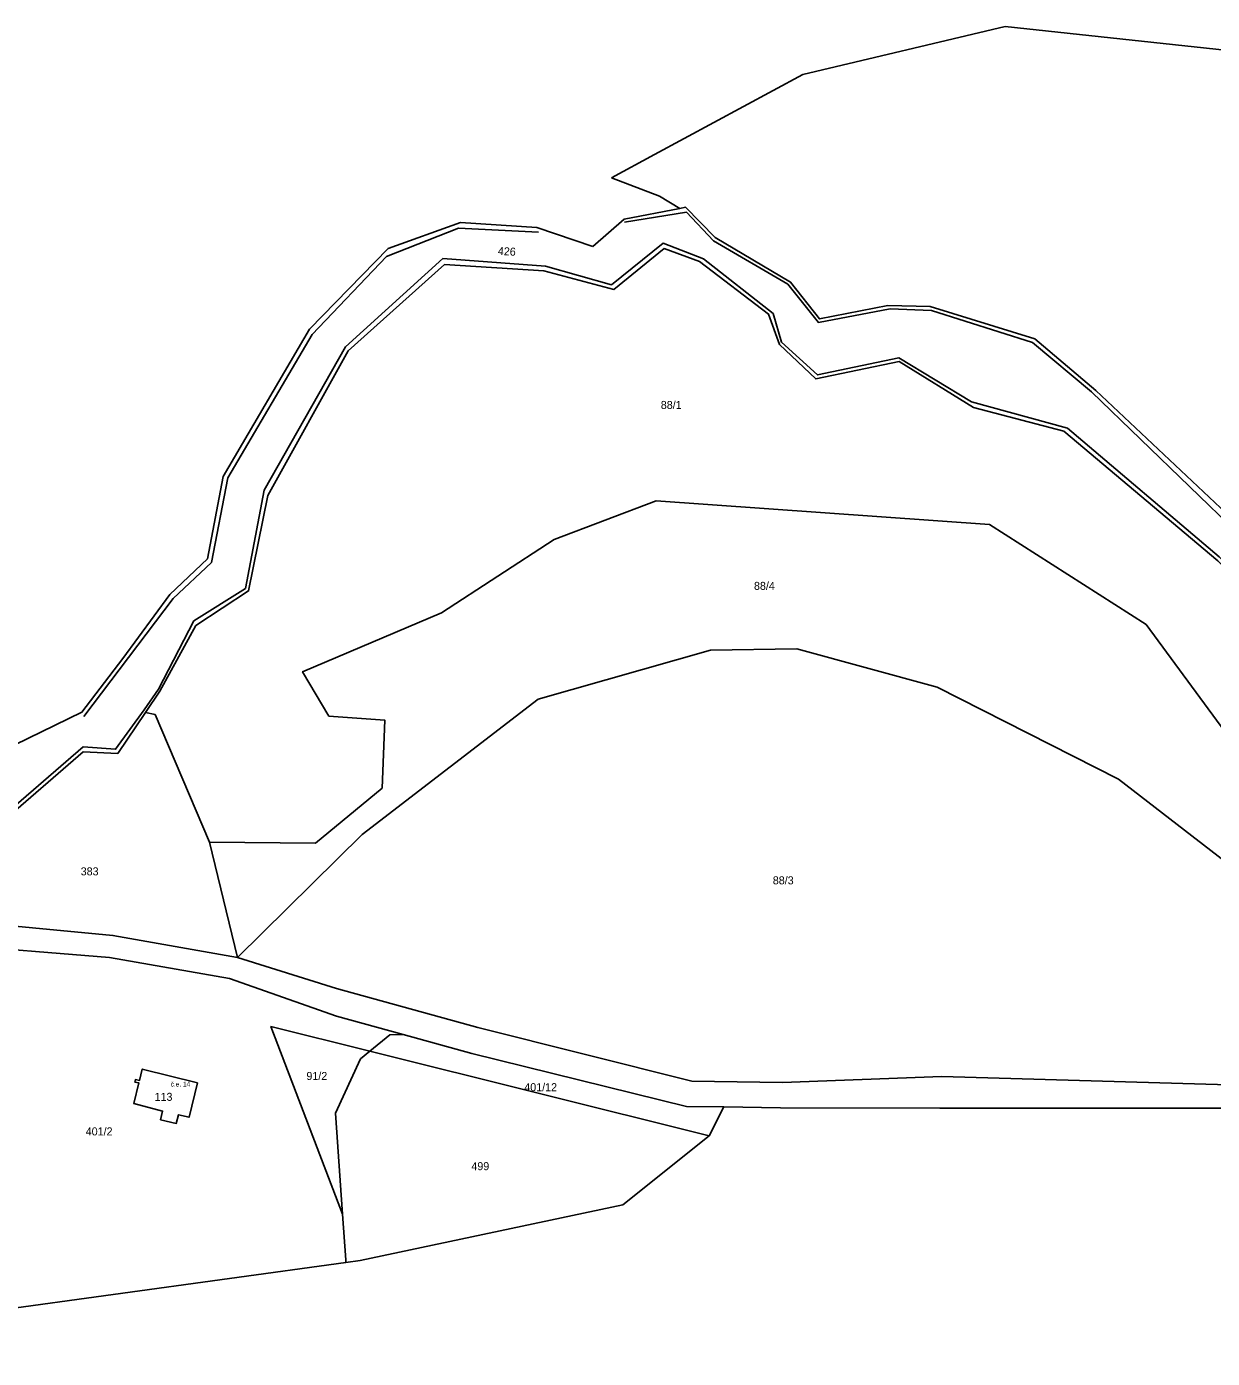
# Model space of a CAD drawing. Extents: x -880531 to -877616, y -1023932 to -1021350.
# Drawn here: x -879285.2 to -879033.3, y -1022577.9 to -1022295 of the extents above; entities that cross this region are included whole.
import ezdxf

# ---------------------------------------------------------------- set-up
doc = ezdxf.new("R2010")
doc.units = 0
for name, color, linetype in [('Definiční body', 7, 'Continuous'), ('Hranice parcel', 7, 'Continuous'), ('Parcelní čísla', 7, 'Continuous'), ('Polygon budovy', 7, 'Continuous'), ('Vnitřní kresba', 7, 'Continuous')]:
    doc.layers.add(name, color=color, linetype=linetype)

msp = doc.modelspace()

# ---------------------------------------------------------------- linework, layer by layer
at = {"layer": 'Hranice parcel'}
for p, q in [((-879151.81, -1022322.15), (-879160.92, -1022327.07)), ((-879160.92, -1022327.07), (-879150.75, -1022330.99)), ((-879150.75, -1022330.99), (-879146.4, -1022333.58)), ((-879146.4, -1022333.58), (-879158.22, -1022335.9)), ((-879176.78, -1022337.61), (-879193.03, -1022336.61)), ((-879158.22, -1022335.9), (-879164.92, -1022341.71)), ((-879164.92, -1022341.71), (-879176.78, -1022337.61)), ((-879254.77, -1022415.62), (-879264.75, -1022429.21)), ((-879259.95, -1022440.7), (-879265.79, -1022449.37)), ((-879246.33, -1022468.23), (-879240.35, -1022492.73)), ((-879214.28, -1022514.25), (-879212.3, -1022512.64)), ((-879212.3, -1022512.64), (-879140.2, -1022530.61)), ((-879137.04, -1022524.47), (-879140.2, -1022530.61)), ((-879217.39, -1022556.97), (-879218.05, -1022547.29)), ((-879217.35, -1022557.49), (-879364.9, -1022577.89)), ((-879217.35, -1022557.49), (-879217.39, -1022556.97))]:
    msp.add_line(p, q, dxfattribs=at)
for points in [[(-878982.43, -1022318.67), (-879021.4, -1022300.98), (-879077.31, -1022294.97), (-879120.32, -1022305.15), (-879151.81, -1022322.15)], [(-879146.4, -1022333.58), (-879145.24, -1022333.35), (-879138.95, -1022339.75), (-879122.89, -1022349.24), (-879116.77, -1022357.07), (-879102.22, -1022354.24), (-879093.28, -1022354.46), (-879071.03, -1022361.28), (-879058.07, -1022372.29), (-879026.73, -1022401.71), (-878991.96, -1022434.26), (-878975.52, -1022443.78), (-878906.92, -1022482.11)], [(-879193.03, -1022336.61), (-879208.36, -1022342.07), (-879225.07, -1022359.23), (-879243.4, -1022390.51), (-879246.72, -1022408.02), (-879254.77, -1022415.62)], [(-879099.81, -1022366.11), (-879117.54, -1022369.81), (-879125.28, -1022362.52), (-879127.61, -1022356.05), (-879142.22, -1022344.89), (-879149.78, -1022342.12), (-879160.43, -1022350.81), (-879175.32, -1022346.83), (-879196.44, -1022345.53), (-879216.89, -1022363.83), (-879233.92, -1022394.6), (-879238.02, -1022414.84), (-879249.26, -1022422.2), (-879256.89, -1022436.17), (-879259.95, -1022440.7)], [(-879064.88, -1022380.92), (-879084.02, -1022375.86), (-879099.81, -1022366.11)], [(-878905.93, -1022494.73), (-878974.79, -1022454.7), (-878999.79, -1022439.69), (-879032.14, -1022408.46), (-879064.88, -1022380.92)], [(-879246.33, -1022468.23), (-879223.81, -1022468.41), (-879209.64, -1022456.73), (-879209.06, -1022442.32), (-879220.96, -1022441.45), (-879226.56, -1022432.02), (-879197.08, -1022419.54), (-879173.11, -1022403.96), (-879151.46, -1022395.72), (-879080.65, -1022400.74), (-879047.37, -1022421.96), (-879025.33, -1022451.91), (-879027.21, -1022459.61), (-878985.13, -1022493.99), (-878968.86, -1022531.3)], [(-878968.86, -1022531.3), (-878987.7, -1022508.24), (-879019.63, -1022480.84), (-879053.22, -1022454.85), (-879091.78, -1022435.29), (-879121.6, -1022427.16), (-879139.91, -1022427.41), (-879176.5, -1022437.82), (-879213.92, -1022466.57), (-879240.35, -1022492.73)], [(-879264.75, -1022429.21), (-879273.42, -1022440.64), (-879296.28, -1022451.71)], [(-879259.95, -1022440.7), (-879257.88, -1022441.09), (-879246.33, -1022468.23)], [(-879265.79, -1022449.37), (-879273.18, -1022449.04), (-879290.63, -1022464.2), (-879312.6, -1022473.29), (-879330.15, -1022473.16), (-879342.53, -1022475.91)], [(-879342.53, -1022475.91), (-879301.02, -1022484.77), (-879266.84, -1022488.04), (-879240.35, -1022492.73)], [(-879205.21, -1022509.09), (-879219.34, -1022505.17), (-879242.06, -1022497.17), (-879267.55, -1022492.75), (-879302.54, -1022489.92), (-879315.42, -1022487.17)], [(-879240.35, -1022492.73), (-879219.37, -1022499.31), (-879189.31, -1022507.6), (-879143.86, -1022518.99), (-879124.64, -1022519.3), (-879090.74, -1022517.98), (-879029.81, -1022519.8), (-878968.86, -1022531.3)], [(-879212.3, -1022512.64), (-879233.27, -1022507.42), (-879218.05, -1022547.29)], [(-879212.3, -1022512.64), (-879208.03, -1022509.18), (-879205.21, -1022509.09)], [(-879205.21, -1022509.09), (-879190.61, -1022513.15), (-879145.04, -1022524.35), (-879137.04, -1022524.47)], [(-879218.05, -1022547.29), (-879219.54, -1022525.8), (-879214.28, -1022514.25)], [(-879250.67, -1022526.68), (-879252.94, -1022526.13), (-879253.4, -1022527.97), (-879256.73, -1022527.19), (-879256.3, -1022525.37), (-879262.38, -1022523.78), (-879261.31, -1022519.37), (-879262.17, -1022519.19), (-879262.06, -1022518.65), (-879261.18, -1022518.84), (-879260.6, -1022516.43), (-879248.88, -1022519.37), (-879250.67, -1022526.68)], [(-878950.5, -1022545.95), (-878971.2, -1022539.15), (-879029.87, -1022524.72), (-879091.18, -1022524.72), (-879125.05, -1022524.64), (-879137.04, -1022524.47)], [(-879140.2, -1022530.61), (-879158.56, -1022545.26), (-879214.32, -1022557.07), (-879217.35, -1022557.49)]]:
    msp.add_lwpolyline(points, dxfattribs=at)
at = {"layer": 'Polygon budovy'}
msp.add_lwpolyline([(-879262.38, -1022523.78), (-879256.3, -1022525.37), (-879256.73, -1022527.19), (-879253.4, -1022527.97), (-879252.94, -1022526.13), (-879250.67, -1022526.68), (-879248.88, -1022519.37), (-879260.6, -1022516.43), (-879261.18, -1022518.84), (-879262.06, -1022518.65), (-879262.17, -1022519.19), (-879261.31, -1022519.37)], close=True, dxfattribs=at)
at = {"layer": 'Vnitřní kresba'}
for p, q in [((-879193.4, -1022337.78), (-879208.72, -1022343.77)), ((-879176.43, -1022338.6), (-879193.4, -1022337.78)), ((-879208.72, -1022343.77), (-879224.51, -1022360.39)), ((-879224.51, -1022360.39), (-879242.46, -1022390.81)), ((-879242.46, -1022390.81), (-879245.91, -1022408.84)), ((-879245.91, -1022408.84), (-879254.03, -1022416.46)), ((-879254.03, -1022416.46), (-879273.04, -1022441.55))]:
    msp.add_line(p, q, dxfattribs=at)
for points in [[(-879027.78, -1022402.72), (-879058.96, -1022372.59), (-879071.52, -1022362.09), (-879092.98, -1022355.25), (-879101.73, -1022354.93), (-879116.99, -1022357.79), (-879123.51, -1022349.68), (-879139.25, -1022340.45), (-879144.98, -1022334.41), (-879158.17, -1022336.48)], [(-879160.96, -1022349.83), (-879149.97, -1022340.97), (-879141.38, -1022344.31), (-879126.59, -1022355.93), (-879124.84, -1022361.97), (-879117.21, -1022368.97), (-879099.88, -1022365.31), (-879084.46, -1022374.7), (-879064.11, -1022380.26), (-879031.83, -1022407.63), (-878998.37, -1022439.56), (-878906.15, -1022493.65), (-878902.18, -1022495.4), (-878889.14, -1022501.28), (-878867.5, -1022509.14)], [(-879291.15, -1022463.47), (-879273.18, -1022447.99), (-879266.28, -1022448.5), (-879260.22, -1022440.08), (-879257.19, -1022435.7), (-879249.62, -1022421.23), (-879238.69, -1022414.32), (-879234.74, -1022393.41), (-879217.41, -1022363.03), (-879196.74, -1022344.26), (-879174.95, -1022345.85), (-879160.96, -1022349.83)]]:
    msp.add_lwpolyline(points, dxfattribs=at)

# ---------------------------------------------------------------- texts
at = {"layer": 'Definiční body'}
msp.add_text('č.e. 14', height=1, dxfattribs=at).set_placement((-879254.57, -1022520.14))
at = {"layer": 'Parcelní čísla'}
msp.add_text('426', height=1.7, rotation=357, dxfattribs=at).set_placement((-879185.104, -1022343.458))
for s, p in [('88/1', (-879150.46, -1022376.19)), ('88/4', (-879130.67, -1022414.63)), ('383', (-879273.68, -1022475.28)), ('88/3', (-879126.67, -1022477.19)), ('91/2', (-879225.74, -1022518.75)), ('401/12', (-879179.458, -1022521.13)), ('113', (-879257.987, -1022523.18)), ('401/2', (-879272.61, -1022530.52)), ('499', (-879190.699, -1022537.91))]:
    msp.add_text(s, height=1.7, dxfattribs=at).set_placement(p)

doc.saveas('drawing.dxf')
